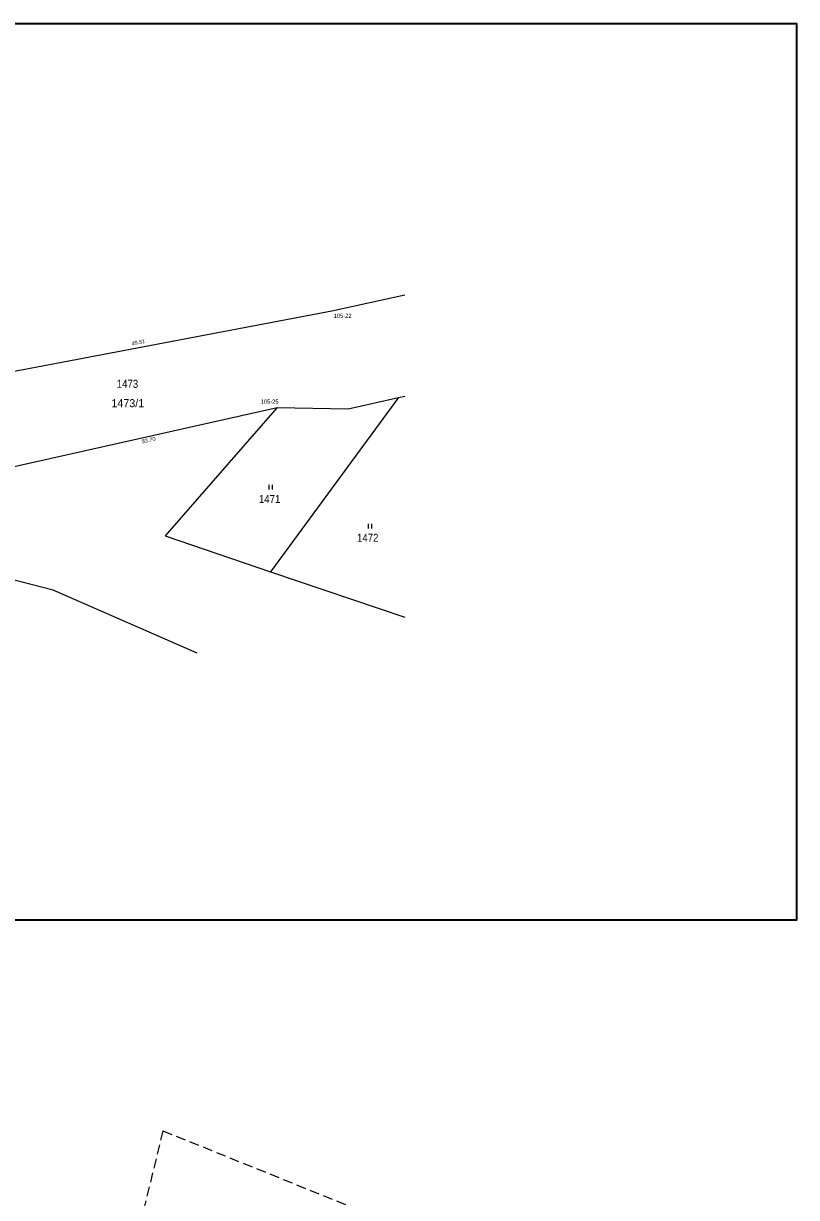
# Model space of a CAD drawing. Extents: x -871901 to -870967, y -1075952 to -1074892.
# Drawn here: x -871383.9 to -871287.3, y -1075153 to -1075006.4 of the extents above; entities that cross this region are included whole.
import ezdxf
from ezdxf.enums import TextEntityAlignment as Align

# ---------------------------------------------------------------- set-up
doc = ezdxf.new("R2010")
doc.units = 0
doc.header["$LTSCALE"] = 0.4
doc.linetypes.add('MEDIUM_DASHED', pattern=[4.5, 3, -1.5])
for name, color, linetype, lineweight in [('1', 7, 'Continuous', 25), ('12', 7, 'MEDIUM_DASHED', 25), ('25', 7, 'Continuous', 25), ('55', 7, 'Continuous', 35), ('62', 7, 'Continuous', 25)]:
    doc.layers.add(name, color=color, linetype=linetype, lineweight=lineweight)
doc.layers.add('18', color=7, linetype='Continuous')
doc.layers.add('54', color=7, linetype='Continuous')

msp = doc.modelspace()

# ---------------------------------------------------------------- linework, layer by layer
at = {"layer": '1'}
for p, q in [((-871345.38, -1075042.25), (-871336.26, -1075040.27)), ((-871385.08, -1075061.72), (-871352.22, -1075054.34)), ((-871337.04, -1075053.09), (-871353.03, -1075074.84)), ((-871380.21, -1075077.17), (-871395.86, -1075073.06)), ((-871362.21, -1075085.02), (-871380.21, -1075077.17))]:
    msp.add_line(p, q, dxfattribs=at)
for points in [[(-871405.48, -1075053.67), (-871394.04, -1075051.49), (-871345.38, -1075042.25)], [(-871352.22, -1075054.34), (-871343.35, -1075054.48), (-871337.04, -1075053.09), (-871336.26, -1075052.92)], [(-871352.22, -1075054.34), (-871366.22, -1075070.37), (-871353.03, -1075074.84), (-871336.26, -1075080.53)]]:
    msp.add_lwpolyline(points, dxfattribs=at)
at = {"layer": '12'}
msp.add_line((-871366.48, -1075144.68), (-871287.54, -1075176.57), dxfattribs=at)
msp.add_lwpolyline([(-871366.48, -1075144.68), (-871372.59, -1075169.57), (-871383.31, -1075211.56)], dxfattribs=at)
at = {"layer": '25'}
for p, q in [((-871353.206, -1075064.575), (-871353.206, -1075063.975)), ((-871352.793, -1075064.575), (-871352.793, -1075063.975)), ((-871340.806, -1075069.465), (-871340.806, -1075068.865)), ((-871340.393, -1075069.465), (-871340.393, -1075068.865))]:
    msp.add_line(p, q, dxfattribs=at)
at = {"layer": '55'}
msp.add_lwpolyline([(-871449.33, -1075118.36), (-871449.33, -1075006.36), (-871287.33, -1075006.36), (-871287.33, -1075118.36)], close=True, dxfattribs=at)

# ---------------------------------------------------------------- texts
at = {"layer": '18', "width": 0.9}
for s, p in [('1473', (-871372.25, -1075051.87)), ('1471', (-871354.49, -1075066.26)), ('1472', (-871342.24, -1075071.11))]:
    msp.add_text(s, height=1, dxfattribs=at).set_placement(p)
at = {"layer": '54', "width": 0.95}
for s, p in [('105-22', (-871345.15, -1075043.13)), ('105-25', (-871354.27, -1075053.85))]:
    msp.add_text(s, height=0.52, dxfattribs=at).set_placement(p)
at = {"layer": '54'}
for s, rotation, width, p in [('49.51', 10.7, 1.05, (-871369.5146, -1075046.4226)), ('33.70', 12.6, 1.1, (-871368.2224, -1075058.6333))]:
    msp.add_text(s, height=0.48, rotation=rotation, dxfattribs=dict(at, width=width)).set_placement(p, align=Align.CENTER)
at = {"layer": '62'}
msp.add_text('1473/1', height=1, dxfattribs=at).set_placement((-871372.91, -1075054.29))

doc.saveas('drawing.dxf')
